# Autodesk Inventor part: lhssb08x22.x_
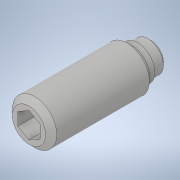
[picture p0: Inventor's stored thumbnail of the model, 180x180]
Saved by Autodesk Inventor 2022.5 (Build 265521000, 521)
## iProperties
Created: 2021-02
Part Number: lhssb08x22.x_
Material: 一般
Document SubType Name: Modeling
Designer: ImaoCorp
Density: 1 g/cm^3
Appearance: 既定
Sending System: SOLIDWORKS 2019-2019304
MC: AMD64
MC_MODEL: Intel64 Family 6 Model 60 Stepping 3, GenuineIntel
OS: Windows_NT
FRU: Parasolid Version 31.0, build 290,  9- 1-2019
FORMAT: text
GUISE: transmit
KEY: lhssb08x22
FILE: lhssb08x22.x_t
DATE: Mon Feb 22 14:56:03 2021
Author: ImaoCorp
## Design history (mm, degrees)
feature "Base1"
node "ソリッド1"
